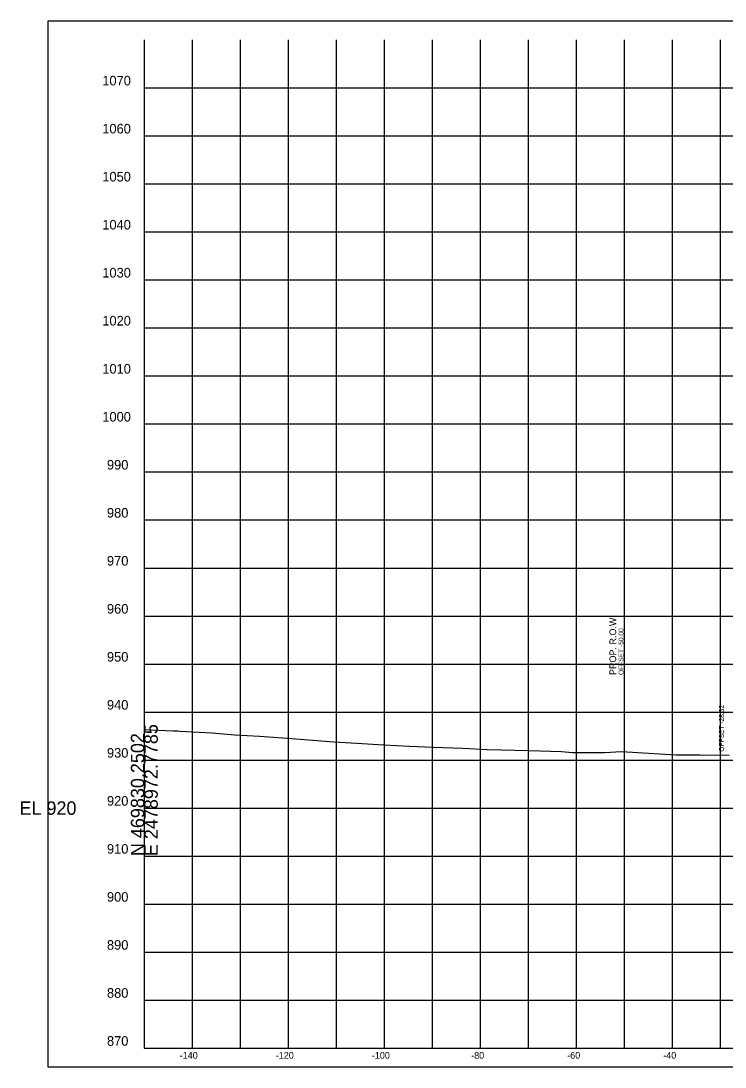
# Model space of a CAD drawing. Extents: x -26 to 2478923, y -10 to 469990.
# Drawn here: x -25.7 to 120.9, y 1446.1 to 1663.9 of the extents above; entities that cross this region are included whole.
import ezdxf

# ---------------------------------------------------------------- set-up
doc = ezdxf.new("R2010")
doc.units = 0
for name, color, linetype in [('DESIGN - ROW - Right-of-Way and Easement Labels', 7, 'Continuous'), ('DESIGN - ROW - Right-of-Way Linework', 7, 'Continuous'), ('DESIGN - SHEET - Corner Text', 7, 'Continuous'), ('DESIGN - SHEET - Light Grid', 7, 'Continuous'), ('DESIGN - SHEET - Linework', 7, 'Continuous'), ('DESIGN - SHEET - Plot Shape', 7, 'Continuous'), ('DESIGN - TYPICAL - Slope Tie Text', 7, 'Continuous'), ('SURVEY - GROUND - Top of Ground', 7, 'Continuous')]:
    doc.layers.add(name, color=color, linetype=linetype)

msp = doc.modelspace()

# ---------------------------------------------------------------- linework, layer by layer
at = {"layer": 'DESIGN - ROW - Right-of-Way Linework'}
msp.add_line((100, 1511.71), (100, 1543.71), dxfattribs=at)
at = {"layer": 'DESIGN - SHEET - Light Grid'}
msp.add_line((0, 1500), (150, 1500), dxfattribs=at)
at = {"layer": 'DESIGN - SHEET - Linework'}
for p, q in [((10, 1450), (10, 1660)), ((10, 1450), (10, 1660)), ((10, 1450), (10, 1660)), ((10, 1450), (10, 1660)), ((20, 1450), (20, 1660)), ((20, 1450), (20, 1660)), ((20, 1450), (20, 1660)), ((20, 1450), (20, 1660)), ((30, 1450), (30, 1660)), ((30, 1450), (30, 1660)), ((30, 1450), (30, 1660)), ((30, 1450), (30, 1660)), ((40, 1450), (40, 1660)), ((40, 1450), (40, 1660)), ((40, 1450), (40, 1660)), ((40, 1450), (40, 1660)), ((50, 1450), (50, 1660)), ((50, 1450), (50, 1660)), ((50, 1450), (50, 1660)), ((50, 1450), (50, 1660)), ((60, 1450), (60, 1660)), ((60, 1450), (60, 1660)), ((60, 1450), (60, 1660)), ((60, 1450), (60, 1660)), ((70, 1450), (70, 1660)), ((70, 1450), (70, 1660)), ((70, 1450), (70, 1660)), ((70, 1450), (70, 1660)), ((80, 1450), (80, 1660)), ((80, 1450), (80, 1660)), ((80, 1450), (80, 1660)), ((80, 1450), (80, 1660)), ((90, 1450), (90, 1660)), ((90, 1450), (90, 1660)), ((90, 1450), (90, 1660)), ((90, 1450), (90, 1660)), ((100, 1450), (100, 1660)), ((100, 1450), (100, 1660)), ((100, 1450), (100, 1660)), ((100, 1450), (100, 1660)), ((110, 1450), (110, 1660)), ((110, 1450), (110, 1660)), ((110, 1450), (110, 1660)), ((110, 1450), (110, 1660)), ((120, 1450), (120, 1660)), ((120, 1450), (120, 1660)), ((120, 1450), (120, 1660)), ((120, 1450), (120, 1660)), ((0, 1650), (300, 1650)), ((0, 1650), (300, 1650)), ((0, 1650), (300, 1650)), ((0, 1650), (300, 1650)), ((0, 1640), (300, 1640)), ((0, 1640), (300, 1640)), ((0, 1640), (300, 1640)), ((0, 1640), (300, 1640)), ((0, 1630), (300, 1630)), ((0, 1630), (300, 1630)), ((0, 1630), (300, 1630)), ((0, 1630), (300, 1630)), ((0, 1620), (300, 1620)), ((0, 1620), (300, 1620)), ((0, 1620), (300, 1620)), ((0, 1620), (300, 1620)), ((0, 1610), (300, 1610)), ((0, 1610), (300, 1610)), ((0, 1610), (300, 1610)), ((0, 1610), (300, 1610)), ((0, 1600), (300, 1600)), ((0, 1600), (300, 1600)), ((0, 1600), (300, 1600)), ((0, 1600), (300, 1600)), ((0, 1590), (300, 1590)), ((0, 1590), (300, 1590)), ((0, 1590), (300, 1590)), ((0, 1590), (300, 1590)), ((0, 1580), (300, 1580)), ((0, 1580), (300, 1580)), ((0, 1580), (300, 1580)), ((0, 1580), (300, 1580)), ((0, 1570), (300, 1570)), ((0, 1570), (300, 1570)), ((0, 1570), (300, 1570)), ((0, 1570), (300, 1570)), ((0, 1560), (300, 1560)), ((0, 1560), (300, 1560)), ((0, 1560), (300, 1560)), ((0, 1560), (300, 1560)), ((0, 1550), (300, 1550)), ((0, 1550), (300, 1550)), ((0, 1550), (300, 1550)), ((0, 1550), (300, 1550)), ((0, 1540), (300, 1540)), ((0, 1540), (300, 1540)), ((0, 1540), (300, 1540)), ((0, 1540), (300, 1540)), ((0, 1530), (300, 1530)), ((0, 1530), (300, 1530)), ((0, 1530), (300, 1530)), ((0, 1530), (300, 1530)), ((0, 1520), (300, 1520)), ((0, 1520), (300, 1520)), ((0, 1520), (300, 1520)), ((0, 1520), (300, 1520)), ((0, 1510), (300, 1510)), ((0, 1510), (300, 1510)), ((0, 1510), (300, 1510)), ((0, 1510), (300, 1510)), ((0, 1500), (300, 1500)), ((0, 1500), (300, 1500)), ((0, 1500), (300, 1500)), ((0, 1500), (300, 1500)), ((0, 1490), (300, 1490)), ((0, 1490), (300, 1490)), ((0, 1490), (300, 1490)), ((0, 1490), (300, 1490)), ((0, 1480), (300, 1480)), ((0, 1480), (300, 1480)), ((0, 1480), (300, 1480)), ((0, 1480), (300, 1480)), ((0, 1470), (300, 1470)), ((0, 1470), (300, 1470)), ((0, 1470), (300, 1470)), ((0, 1470), (300, 1470)), ((0, 1460), (300, 1460)), ((0, 1460), (300, 1460)), ((0, 1460), (300, 1460)), ((0, 1460), (300, 1460))]:
    msp.add_line(p, q, dxfattribs=at)
msp.add_lwpolyline([(0, 1660), (0, 1450), (300, 1450), (300, 1660)], dxfattribs=at)
msp.add_lwpolyline([(0, 1660), (0, 1450), (300, 1450), (300, 1660)], dxfattribs=at)
msp.add_lwpolyline([(0, 1660), (0, 1450), (300, 1450), (300, 1660)], dxfattribs=at)
msp.add_lwpolyline([(0, 1660), (0, 1450), (300, 1450), (300, 1660)], dxfattribs=at)
at = {"layer": 'DESIGN - SHEET - Plot Shape'}
msp.add_lwpolyline([(-20, 1663.94), (320, 1663.94), (320, 1446.06), (-20, 1446.06)], close=True, dxfattribs=at)
msp.add_lwpolyline([(-20, 1663.94), (320, 1663.94), (320, 1446.06), (-20, 1446.06)], close=True, dxfattribs=at)
msp.add_lwpolyline([(-20, 1663.94), (320, 1663.94), (320, 1446.06), (-20, 1446.06)], close=True, dxfattribs=at)
msp.add_lwpolyline([(-20, 1663.94), (320, 1663.94), (320, 1446.06), (-20, 1446.06)], close=True, dxfattribs=at)
at = {"layer": 'SURVEY - GROUND - Top of Ground'}
msp.add_lwpolyline([(0, 1516.36), (6.01, 1516.12), (6.89, 1516.08), (7.36, 1516.05), (14.12, 1515.66), (18.82, 1515.27), (24.01, 1514.95), (30.7, 1514.48), (31.54, 1514.41), (39.43, 1513.82), (44.28, 1513.53), (49.81, 1513.18), (55.23, 1512.92), (60.14, 1512.72), (66.3, 1512.46), (71.37, 1512.22), (80.08, 1512.01), (86.86, 1511.76), (89.15, 1511.57), (95.9, 1511.61), (99.36, 1511.75), (110.67, 1511.12), (115.73, 1511.09), (121.76, 1510.99)], dxfattribs=at)

# ---------------------------------------------------------------- texts
at = {"layer": 'DESIGN - ROW - Right-of-Way and Easement Labels'}
for s, height, p in [('PROP. R.O.W.', 1.4, (98.25, 1527.71)), ('OFFSET -50.00', 1, (99.75, 1527.71))]:
    msp.add_text(s, height=height, rotation=90, dxfattribs=at).set_placement(p)
at = {"layer": 'DESIGN - SHEET - Corner Text'}
for s, height, p in [('1070', 2, (-8.75, 1650.5)), ('1070', 2, (-8.75, 1650.5)), ('1070', 2, (-8.75, 1650.5)), ('1070', 2, (-8.75, 1650.5)), ('1060', 2, (-8.75, 1640.5)), ('1060', 2, (-8.75, 1640.5)), ('1060', 2, (-8.75, 1640.5)), ('1060', 2, (-8.75, 1640.5)), ('1050', 2, (-8.75, 1630.5)), ('1050', 2, (-8.75, 1630.5)), ('1050', 2, (-8.75, 1630.5)), ('1050', 2, (-8.75, 1630.5)), ('1040', 2, (-8.75, 1620.5)), ('1040', 2, (-8.75, 1620.5)), ('1040', 2, (-8.75, 1620.5)), ('1040', 2, (-8.75, 1620.5)), ('1030', 2, (-8.75, 1610.5)), ('1030', 2, (-8.75, 1610.5)), ('1030', 2, (-8.75, 1610.5)), ('1030', 2, (-8.75, 1610.5)), ('1020', 2, (-8.75, 1600.5)), ('1020', 2, (-8.75, 1600.5)), ('1020', 2, (-8.75, 1600.5)), ('1020', 2, (-8.75, 1600.5)), ('1010', 2, (-8.75, 1590.5)), ('1010', 2, (-8.75, 1590.5)), ('1010', 2, (-8.75, 1590.5)), ('1010', 2, (-8.75, 1590.5)), ('1000', 2, (-8.75, 1580.5)), ('1000', 2, (-8.75, 1580.5)), ('1000', 2, (-8.75, 1580.5)), ('1000', 2, (-8.75, 1580.5)), ('990', 2, (-7.78, 1570.5)), ('990', 2, (-7.78, 1570.5)), ('990', 2, (-7.78, 1570.5)), ('990', 2, (-7.78, 1570.5)), ('980', 2, (-7.78, 1560.5)), ('980', 2, (-7.78, 1560.5)), ('980', 2, (-7.78, 1560.5)), ('980', 2, (-7.78, 1560.5)), ('970', 2, (-7.78, 1550.5)), ('970', 2, (-7.78, 1550.5)), ('970', 2, (-7.78, 1550.5)), ('970', 2, (-7.78, 1550.5)), ('960', 2, (-7.78, 1540.5)), ('960', 2, (-7.78, 1540.5)), ('960', 2, (-7.78, 1540.5)), ('960', 2, (-7.78, 1540.5)), ('950', 2, (-7.78, 1530.5)), ('950', 2, (-7.78, 1530.5)), ('950', 2, (-7.78, 1530.5)), ('950', 2, (-7.78, 1530.5)), ('940', 2, (-7.78, 1520.5)), ('940', 2, (-7.78, 1520.5)), ('940', 2, (-7.78, 1520.5)), ('940', 2, (-7.78, 1520.5)), ('930', 2, (-7.78, 1510.5)), ('930', 2, (-7.78, 1510.5)), ('930', 2, (-7.78, 1510.5)), ('930', 2, (-7.78, 1510.5)), ('920', 2, (-7.78, 1500.5)), ('920', 2, (-7.78, 1500.5)), ('920', 2, (-7.78, 1500.5)), ('920', 2, (-7.78, 1500.5)), ('910', 2, (-7.78, 1490.5)), ('910', 2, (-7.78, 1490.5)), ('910', 2, (-7.78, 1490.5)), ('910', 2, (-7.78, 1490.5)), ('900', 2, (-7.78, 1480.5)), ('900', 2, (-7.78, 1480.5)), ('900', 2, (-7.78, 1480.5)), ('900', 2, (-7.78, 1480.5)), ('890', 2, (-7.78, 1470.5)), ('890', 2, (-7.78, 1470.5)), ('890', 2, (-7.78, 1470.5)), ('890', 2, (-7.78, 1470.5)), ('880', 2, (-7.78, 1460.5)), ('880', 2, (-7.78, 1460.5)), ('880', 2, (-7.78, 1460.5)), ('880', 2, (-7.78, 1460.5)), ('870', 2, (-7.78, 1450.5)), ('870', 2, (-7.78, 1450.5)), ('870', 2, (-7.78, 1450.5)), ('870', 2, (-7.78, 1450.5)), ('-140', 1.4, (7.37, 1447.8)), ('-140', 1.4, (7.37, 1447.8)), ('-140', 1.4, (7.37, 1447.8)), ('-140', 1.4, (7.37, 1447.8)), ('-120', 1.4, (27.37, 1447.8)), ('-120', 1.4, (27.37, 1447.8)), ('-120', 1.4, (27.37, 1447.8)), ('-120', 1.4, (27.37, 1447.8)), ('-100', 1.4, (47.37, 1447.8)), ('-100', 1.4, (47.37, 1447.8)), ('-100', 1.4, (47.37, 1447.8)), ('-100', 1.4, (47.37, 1447.8)), ('-80', 1.4, (68.06, 1447.8)), ('-80', 1.4, (68.06, 1447.8)), ('-80', 1.4, (68.06, 1447.8)), ('-80', 1.4, (68.06, 1447.8)), ('-60', 1.4, (88.06, 1447.8)), ('-60', 1.4, (88.06, 1447.8)), ('-60', 1.4, (88.06, 1447.8)), ('-60', 1.4, (88.06, 1447.8)), ('-40', 1.4, (108.06, 1447.8)), ('-40', 1.4, (108.06, 1447.8)), ('-40', 1.4, (108.06, 1447.8)), ('-40', 1.4, (108.06, 1447.8))]:
    msp.add_text(s, height=height, dxfattribs=at).set_placement(p)
at = {"layer": 'DESIGN - SHEET - Light Grid'}
for s, p in [('E 2478972.7785', (2.8, 1490)), ('N 469830.2502', (0, 1490))]:
    msp.add_text(s, height=2.8, rotation=90, dxfattribs=at).set_placement(p)
msp.add_text('EL 920', height=2.8, dxfattribs=at).set_placement((-26, 1498.6))
at = {"layer": 'DESIGN - TYPICAL - Slope Tie Text'}
msp.add_text('OFFSET -28.32', height=1, rotation=90, dxfattribs=at).set_placement((120.68, 1511.74))

doc.saveas('drawing.dxf')
